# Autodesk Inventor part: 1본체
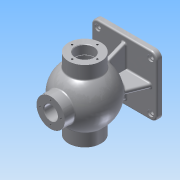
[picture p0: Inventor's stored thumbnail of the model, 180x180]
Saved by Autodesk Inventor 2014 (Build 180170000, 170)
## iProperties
Created: 2017-01
Part Number: 1본체
Material: Aluminum 6061
Document SubType Name: Modeling
Designer: ksu
Density: 2.71 g/cm^3
Appearance: Aluminum - Flat
Mass: 1508.58 g
Surface Area: 1156.25 cm^2
Volume: 556.67 cm^3
Author: ksu
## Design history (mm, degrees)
sketch "Sketch1"
  geometry: L1 (-62.5, -57.5)-(62.5, -57.5); L2 (62.5, -57.5)-(62.5, 57.5); L3 (62.5, 57.5)-(-62.5, 57.5); L4 (-62.5, 57.5)-(-62.5, -57.5); L5 (-62.5, -57.5)-(62.5, 57.5); L6 (62.5, -57.5)-(-62.5, 57.5); 1 further point
  constraints: 12 end point, 2 midpoint, 2 parallel, 1 horizontal, 1 perpendicular
  dimensions: "d0" = 125 distance of L2.end L3.end; "d1" = 115 distance of L1.end L2.end
extrude "Extrusion1" new body sketch "Sketch1" distance "d2" = 10; taper "d3" = 0 deg
sketch "Sketch2"
  geometry: L1 (-57.5, 0)-(57.5, 0) reference; L2 (0, 138)-(0, 128); L3 (0, 42)-(0, 28.594); L4 (0, 85)-(0, 106.982); A1 r 53 centre (0, 85) between (0, 138) and (0, 32); A2 r 43 centre (0, 85) between (0, 128) and (0, 42); 1 further point
  constraints: 6 end point, 4 point on circle, 2 centre point, 2 collinear, 1 coincident, 1 perpendicular, 1 point on line
  dimensions: "d5" = 85 distance from line of L1 A1.centre; "d6" = 106 diameter of A1; "d7" = 86 diameter of A2
revolve "Revolution1" sketch "Sketch2" stored, may be unused: angle "d8" = 90 deg
workplane "Work Plane2"
sketch "Sketch3"
  geometry: C1 r 31 at (0, 85); 1 further point
  constraints: 1 centre point
  dimensions: "d10" = 85 distance of point (0, 0) C1.centre; "d20" = 62 diameter of C1
extrude "Extrusion2" join sketch "Sketch3" distance "d11" = 136; taper "d12" = 0 deg
workplane "Work Plane3"
sketch "Sketch4"
  geometry: C1 r 27 at (0, 0); 1 further point
  constraints: 1 centre point, 1 coincident
  dimensions: "d14" = 54 diameter of C1
extrude "Extrusion3" join sketch "Sketch4" distance "d15" = 25; taper "d16" = 0 deg
sketch "Sketch5"
  geometry: L1 (0, 85)-(0, 128); L2 (0, 128)-(0, 42); A1 r 43 centre (0, 85) between (0, 128) and (0, 42); 1 further point
  constraints: 4 end point, 2 point on circle, 1 centre point, 1 collinear, 1 vertical
  dimensions: "d17" = 85 distance of point (0, 0) L1.start; "d18" = 86 diameter of A1
revolve "Revolution2" sketch "Sketch5" stored, may be unused: angle "d19" = 90 deg
sketch "Sketch6"
  geometry: C1 r 31 at (0, 0) reference; 2 further points
  constraints: 1 coincident
hole "Hole1" sketch "Sketch6" at (0, 0) diameter "d21" = 35; stored, may be unused: countersink angle "d25" = 90 deg, drill point angle "d27" = 118 deg; dims "d22" = 6, "d23" = 4, "d24" = 2, "d26" = 8
sketch "Sketch7"
  geometry: C1 r 27 at (0, 0) reference; 1 further point
  constraints: 1 coincident
hole "Hole2" sketch "Sketch7" at (0, 0) diameter "d28" = 26; stored, may be unused: countersink angle "d32" = 90 deg, drill point angle "d34" = 118 deg; dims "d29" = 6, "d30" = 4, "d31" = 2, "d33" = 30
sketch "Sketch8"
  geometry: L1 (42.988, 116)-(68, 116) reference; L2 (68, 116)-(68, 102.5) reference; L3 (68, 102.5)-(39.278, 102.5) reference; L4 (13, 125.988)-(13, 150) reference; L5 (13, 150)-(27, 150) reference; L6 (27, 150)-(27, 130.607) reference; L7 (-68, 116)-(-42.988, 116) reference; L8 (-27, 130.607)-(-27, 150) reference; L9 (-27, 150)-(-13, 150) reference; L10 (-13, 150)-(-13, 125.988) reference; L11 (-39.278, 102.5)-(-68, 102.5) reference; L12 (-68, 102.5)-(-68, 116) reference; L13 (-42.988, 54)-(-68, 54) reference; L14 (-68, 54)-(-68, 67.5) reference; L15 (-68, 67.5)-(-39.278, 67.5) reference; L16 (39.278, 67.5)-(68, 67.5) reference; L17 (68, 67.5)-(68, 54) reference; L18 (68, 54)-(42.988, 54) reference; L19 (-57.5, 0)-(-57.5, 10) reference; L20 (-57.5, 10)-(57.5, 10) reference; L21 (57.5, 10)-(57.5, 0) reference; L22 (57.5, 0)-(-57.5, 0) reference; L23 (-47.5, 10)-(-31.419, 49.803); L24 (47.5, 10)-(31.419, 49.803); A1 r 43 centre (0, 85) between (39.278, 102.5) and (13, 125.988) reference; A2 r 53 centre (0, 85) between (42.988, 116) and (27, 130.607) reference; A3 r 53 centre (0, 85) between (-27, 130.607) and (-42.988, 116) reference; A4 r 43 centre (0, 85) between (-13, 125.988) and (-39.278, 102.5) reference; A5 r 43 centre (0, 85) between (-39.278, 67.5) and (0, 42) reference; A6 r 43 centre (0, 85) between (0, 42) and (39.278, 67.5) reference; A7 r 53 centre (0, 85) between (-42.988, 54) and (0, 32) reference; A8 r 53 centre (0, 85) between (0, 32) and (42.988, 54) reference; A9 r 47.181 centre (0, 85) between (-31.419, 49.803) and (31.419, 49.803); 1 further point
  constraints: 4 end point, 2 point on circle, 1 centre point, 1 coincident, 1 point on line
  dimensions: "d35" = 10 distance from line of L19 L23.start; "d36" = 22 deg angle of L19 L23
feature "Rib1" sketch "Sketch8" dims "d37" = 1, "d38" = 8, "d39" = 0, "d40" = 0, "d41" = 1, "d42" = 1
sketch "Sketch9"
  geometry: L1 (27, 150)-(27, 130.607) reference; L2 (4, 32.151)-(4, 10) reference; L3 (4, 10)-(62.5, 10) reference; L4 (62.5, 10)-(62.5, 0) reference; L5 (62.5, 0)-(-62.5, 0) reference; L6 (-62.5, 0)-(-62.5, 10) reference; L7 (-62.5, 10)-(-4, 10) reference; L8 (-4, 10)-(-4, 32.151) reference; L9 (-27, 130.607)-(-27, 150) reference; L10 (-27, 150)-(-13, 150) reference; L11 (-13, 150)-(-13, 125.988) reference; L12 (13, 125.988)-(13, 150) reference; L13 (13, 150)-(27, 150) reference; L14 (-52.5, 10)-(-35.383, 52.366); L15 (52.5, 10)-(35.383, 52.366); A1 r 53 centre (0, 85) between (4, 32.151) and (27, 130.607) reference; A2 r 53 centre (0, 85) between (-27, 130.607) and (-4, 32.151) reference; A3 r 43 centre (0, 85) between (-13, 125.988) and (0, 42) reference; A4 r 43 centre (0, 85) between (0, 42) and (13, 125.988) reference; A5 r 48.134 centre (0, 85) between (-35.383, 52.366) and (35.383, 52.366); 1 further point
  constraints: 4 end point, 2 point on circle, 1 centre point, 1 coincident, 1 point on line
  dimensions: "d43" = 10 distance from line of L6 L14.start; "d44" = 22 deg angle of L6 L14
feature "Rib2" sketch "Sketch9" dims "d45" = 1, "d46" = 8, "d47" = 0, "d48" = 0, "d49" = 1, "d50" = 1
chamfer "Chamfer1" distance "d51" = 1; stored, may be unused: second distance "d52" = 2, angle "d53" = 45 deg
chamfer "Chamfer2" distance "d54" = 1; stored, may be unused: second distance "d55" = 2, angle "d56" = 45 deg
chamfer "Chamfer3" distance "d57" = 1; stored, may be unused: second distance "d58" = 2, angle "d59" = 45 deg
sketch "Sketch10"
  geometry: C1 r 18.5 at (0, 0) reference; 3 further points
  constraints: 1 coincident, 1 vertical alignment, 2 other
hole "Hole3" sketch "Sketch10" at (0, 22.5) diameter "d61" = 3.459; stored, may be unused: countersink angle "d65" = 90 deg, drill point angle "d67" = 118 deg; dims "d62" = 12, "d63" = 4, "d64" = 2, "d66" = 15
pattern_circular "Circular Pattern1" dims angle "d69" = 360 deg
sketch "Sketch11"
  geometry: 2 further points
hole "Hole4" sketch "Sketch11" at (0, -24) diameter "d72" = 3.459; stored, may be unused: countersink angle "d76" = 90 deg, drill point angle "d78" = 118 deg; dims "d73" = 16, "d74" = 4, "d75" = 2, "d77" = 19
pattern_circular "Circular Pattern2" dims angle "d80" = 360 deg
sketch "Sketch12"
  geometry: 1 further point
hole "Hole5" sketch "Sketch12" at (0, 20) diameter "d83" = 3.459; stored, may be unused: countersink angle "d87" = 90 deg, drill point angle "d89" = 118 deg; dims "d84" = 9, "d85" = 4, "d86" = 2, "d88" = 11
pattern_circular "Circular Pattern3" dims angle "d91" = 360 deg
sketch "Sketch13"
  geometry: L1 (-27, 130.607)-(-27, 150) reference; L2 (-27, 150)-(-21.73, 150) reference; L3 (-21.73, 150)-(-21.73, 139) reference; L4 (-21.73, 139)-(-20, 137.961) reference; L5 (-20, 137.961)-(-18.271, 139) reference; L6 (-18.271, 139)-(-18.271, 150) reference; L7 (-18.271, 150)-(-14, 150) reference; L8 (-14, 150)-(-13, 149) reference; L9 (-13, 149)-(-13, 125.988) reference; L10 (-39.278, 102.5)-(-67, 102.5) reference; L11 (-67, 102.5)-(-68, 103.5) reference; L12 (-68, 103.5)-(-68, 105.77) reference; L13 (-68, 105.77)-(-53, 105.77) reference; L14 (-53, 105.77)-(-51.961, 107.5) reference; L15 (-51.961, 107.5)-(-53, 109.23) reference; L16 (-53, 109.23)-(-68, 109.23) reference; L17 (-68, 109.23)-(-68, 116) reference; L18 (-68, 116)-(-42.988, 116) reference; L19 (42.988, 116)-(68, 116) reference; L20 (68, 116)-(68, 110.73) reference; L21 (68, 110.73)-(49, 110.73) reference; L22 (49, 110.73)-(47.961, 109) reference; L23 (47.961, 109)-(49, 107.27) reference; L24 (49, 107.27)-(68, 107.27) reference; L25 (68, 107.27)-(68, 103.5) reference; L26 (68, 103.5)-(67, 102.5) reference; L27 (67, 102.5)-(39.278, 102.5) reference; L28 (13, 125.988)-(13, 149) reference; L29 (13, 149)-(14, 150) reference; L30 (14, 150)-(18.271, 150) reference; L31 (18.271, 150)-(18.271, 139) reference; L32 (18.271, 139)-(20, 137.961) reference; L33 (20, 137.961)-(21.73, 139) reference; L34 (21.73, 139)-(21.73, 150) reference; L35 (21.73, 150)-(27, 150) reference; L36 (27, 150)-(27, 130.607) reference; L37 (57.5, 0)-(-57.5, 0) reference; L38 (-57.5, 0)-(-57.5, 10) reference; L39 (-57.5, 10)-(-47.5, 10) reference; L40 (-47.5, 10)-(-33.719, 44.109) reference; L41 (-42.988, 54)-(-68, 54) reference; L42 (-68, 54)-(-68, 60.77) reference; L43 (-68, 60.77)-(-53, 60.77) reference; L44 (-53, 60.77)-(-51.961, 62.5) reference; L45 (-51.961, 62.5)-(-53, 64.23) reference; L46 (-53, 64.23)-(-68, 64.23) reference; L47 (-68, 64.23)-(-68, 66.5) reference; L48 (-68, 66.5)-(-67, 67.5) reference; L49 (-67, 67.5)-(-39.278, 67.5) reference; L50 (39.278, 67.5)-(67, 67.5) reference; L51 (67, 67.5)-(68, 66.5) reference; L52 (68, 66.5)-(68, 62.73) reference; L53 (68, 62.73)-(49, 62.73) reference; L54 (49, 62.73)-(47.961, 61) reference; L55 (47.961, 61)-(49, 59.27) reference; L56 (49, 59.27)-(68, 59.27) reference; L57 (68, 59.27)-(68, 54) reference; L58 (68, 54)-(42.988, 54) reference; L59 (33.719, 44.109)-(47.5, 10) reference; L60 (47.5, 10)-(57.5, 10) reference; L61 (57.5, 10)-(57.5, 0) reference; L62 (0, 85)-(93.74, 85); L63 (52, 103.5)-(52, 85); L64 (68, 66.5)-(68, 103.5) reference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; A1 r 53 centre (0, 85) between (-27, 130.607) and (-42.988, 116) reference; A2 r 43 centre (0, 85) between (-13, 125.988) and (-39.278, 102.5) reference; A3 r 53 centre (0, 85) between (42.988, 116) and (27, 130.607) reference; A4 r 43 centre (0, 85) between (39.278, 102.5) and (13, 125.988) reference; A5 r 53 centre (0, 85) between (-42.988, 54) and (-33.719, 44.109) reference; A6 r 43 centre (0, 85) between (-39.278, 67.5) and (0, 42) reference; A7 r 43 centre (0, 85) between (0, 42) and (39.278, 67.5) reference; A8 r 53 centre (0, 85) between (33.719, 44.109) and (42.988, 54) reference; 1 further point
  constraints: 10 end point, 3 perpendicular, 2 point on line, 1 collinear, 1 parallel
  dimensions: "d93" = 16 distance between parallel lines of L64 L63; "d94" = 37 diameter of L65 L62; "d95" = 1.75 distance between parallel lines of L63 L66
revolve "Revolution3" sketch "Sketch13" stored, may be unused: angle "d96" = 90 deg
fillet "Fillet1" dims "d97" = 12
fillet "Fillet2" dims "d98" = 3
fillet "Fillet3" dims "d99" = 3
fillet "Fillet4" dims "d100" = 3
fillet "Fillet5" dims "d101" = 3
sketch "Sketch15"
  geometry: A1 r 9 centre (50.5, -45.5) between (50.5, -54.5) and (59.5, -45.5) reference; A2 r 9 centre (50.5, 45.5) between (59.5, 45.5) and (50.5, 54.5) reference; A3 r 9 centre (-50.5, 45.5) between (-50.5, 54.5) and (-59.5, 45.5) reference; A4 r 9 centre (-50.5, -45.5) between (-59.5, -45.5) and (-50.5, -54.5) reference; 5 further points
  constraints: 4 coincident
hole "Hole6" sketch "Sketch15" at (-50.5, 45.5), (-50.5, -45.5), (50.5, -45.5), (50.5, 45.5) diameter "d102" = 8; stored, may be unused: countersink angle "d106" = 90 deg, drill point angle "d108" = 118 deg; dims "d103" = 8, "d104" = 12, "d105" = 3, "d107" = 11
workplane "Work Plane6"
fillet "Fillet6" dims "d118" = 3
workplane "Work Plane7"
  workaxis "Work Axis2"
sketch "Sketch20"
  geometry: 1 further point
workplane "Work Plane8"
sketch "Sketch21"
  geometry: L1 (149.212, 58.002)-(190.691, 58.002); L2 (190.691, 58.002)-(190.691, 51.998); L3 (190.691, 51.998)-(149.212, 51.998); L4 (149.212, 51.998)-(149.212, 58.002); L5 (196.952, 65)-(142.952, 65) reference; 2 further points
  constraints: 2 other
  dimensions: "d121" = 10 distance from line of L5 point (169.952, 55)
emboss "Emboss3" sketch "Sketch21" dims "d122" = 0.5, "d123" = 0
body "Solid1"
node "Project Cut Edges1"
node "Project Cut Edges2"
node "Project Cut Edges3"
other parameters: "d9" = 68, "d119" = 180 deg
